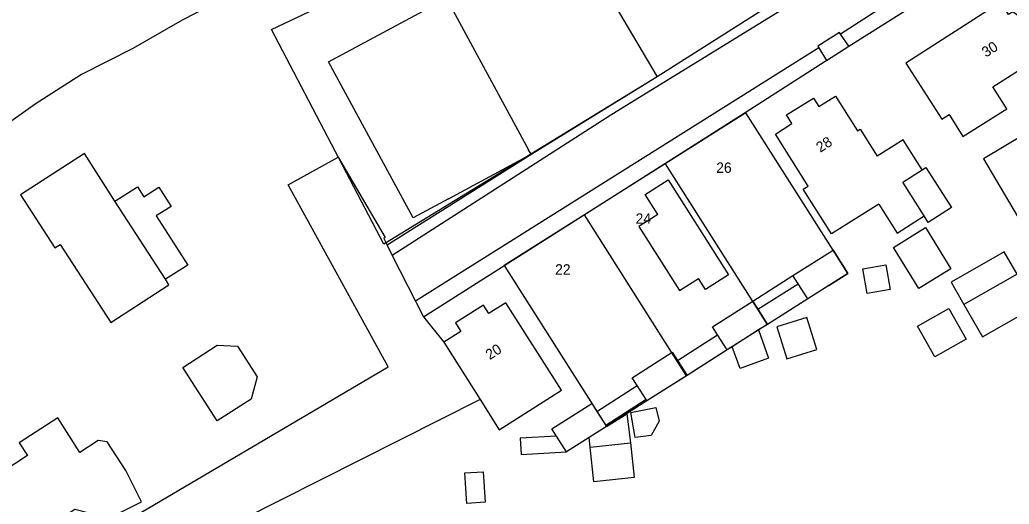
# Model space of a CAD drawing. Extents: x 194485 to 197793, y 468269 to 470822.
# Drawn here: x 195533.1 to 195647.3, y 469392.9 to 469448.8 of the extents above; entities that cross this region are included whole.
import ezdxf

# ---------------------------------------------------------------- set-up
doc = ezdxf.new("R2010")
doc.units = 0
for name, color, linetype in [('BAG standplaatsen grensvlak', 7, 'Continuous'), ('BAG standplaatsen grensvlak LR', 7, 'Continuous'), ('BAG standplaatsen kenmerkpunt', 7, 'Continuous'), ('BGT grensvlak gebouwinstallatie plus 1', 7, 'Continuous'), ('BGT grensvlak onbegroeid terreindeel', 7, 'Continuous'), ('BGT grensvlak overig bouwwerk uitbreiding populatie', 7, 'Continuous'), ('BGT grensvlak pand op maaiveld', 7, 'Continuous'), ('BGT grensvlak pand op maaiveld LR', 7, 'Continuous'), ('BGT grensvlak wegdeel', 7, 'Continuous'), ('BGT tekst huisnummerreeks', 7, 'Continuous')]:
    doc.layers.add(name, color=color, linetype=linetype)

msp = doc.modelspace()

# ---------------------------------------------------------------- linework, layer by layer
at = {"layer": 'BAG standplaatsen grensvlak'}
for p, q in [((195616.89, 469438.07), (195607.58, 469432.19)), ((195607.58, 469432.19), (195598.28, 469426.31)), ((195598.28, 469426.31), (195589.01, 469420.46)), ((195589.01, 469420.46), (195600.82, 469401.86)), ((195626.46, 469418.14), (195628.67, 469419.55)), ((195619.36, 469413.63), (195618.84, 469413.3)), ((195603.25, 469403.4), (195600.82, 469401.86))]:
    msp.add_line(p, q, dxfattribs=at)
for points in [[(195562.14, 469447.72), (195594.39, 469463), (195606.67, 469442.23), (195575.13, 469422.91), (195562.14, 469447.72)], [(195628.67, 469419.55), (195626.97, 469422.23), (195616.89, 469438.07)], [(195626.46, 469418.14), (195624.04, 469416.6), (195619.39, 469413.66), (195619.36, 469413.63)], [(195618.84, 469413.3), (195614.75, 469410.71), (195611.14, 469408.41)], [(195611.14, 469408.41), (195610.11, 469407.76), (195610.07, 469407.73)], [(195610.07, 469407.73), (195605.48, 469404.82), (195603.25, 469403.4)]]:
    msp.add_lwpolyline(points, dxfattribs=at)
at = {"layer": 'BAG standplaatsen grensvlak LR'}
for p, q in [((195607.58, 469432.19), (195619.36, 469413.63)), ((195610.07, 469407.73), (195598.28, 469426.31))]:
    msp.add_line(p, q, dxfattribs=at)
at = {"layer": 'BGT grensvlak gebouwinstallatie plus 1'}
for p, q in [((195544.09, 469427.9), (195546.68, 469429.55)), ((195546.68, 469429.55), (195547.42, 469428.39)), ((195547.42, 469428.39), (195549.15, 469429.49)), ((195549.15, 469429.49), (195550.56, 469427.28)), ((195550.56, 469427.28), (195548.86, 469426.19)), ((195548.86, 469426.19), (195552.49, 469420.49)), ((195633.94, 469422.55), (195637.63, 469424.83)), ((195637.63, 469424.83), (195640.56, 469420.07)), ((195636.86, 469417.8), (195633.94, 469422.55)), ((195552.49, 469420.49), (195549.92, 469418.86)), ((195640.56, 469420.07), (195636.86, 469417.8)), ((195617.69, 469416.34), (195622.33, 469419.29)), ((195618.29, 469415.4), (195622.93, 469418.35)), ((195624.04, 469416.6), (195619.39, 469413.66)), ((195636.71, 469413.45), (195640.33, 469415.49)), ((195640.33, 469415.49), (195642.34, 469411.94)), ((195618.37, 469413.01), (195619.53, 469409.77)), ((195638.71, 469409.9), (195636.71, 469413.45)), ((195609.02, 469409.47), (195613.64, 469412.46)), ((195642.34, 469411.94), (195638.71, 469409.9)), ((195551.92, 469408.69), (195555.88, 469411.24)), ((195555.88, 469411.24), (195558.22, 469411.13)), ((195558.22, 469411.13), (195560.49, 469407.59)), ((195614.75, 469410.71), (195610.11, 469407.76)), ((195616.23, 469408.58), (195615.33, 469411.07)), ((195619.53, 469409.77), (195616.23, 469408.58)), ((195555.9, 469402.51), (195551.92, 469408.69)), ((195560.49, 469407.59), (195559.82, 469405.04)), ((195599.71, 469403.61), (195604.35, 469406.59)), ((195559.82, 469405.04), (195555.9, 469402.51)), ((195605.38, 469404.97), (195600.74, 469401.99)), ((195600.82, 469401.86), (195603.15, 469403.34)), ((195603.15, 469403.34), (195603.6, 469399.99)), ((195598.92, 469399.49), (195598.81, 469400.58))]:
    msp.add_line(p, q, dxfattribs=at)
for points in [[(195648.2, 469419.44), (195646.73, 469422.02), (195640.6, 469418.52), (195642.07, 469415.94)], [(195595.05, 469400.75), (195590.86, 469400.52), (195590.96, 469398.63), (195596.21, 469398.93)], [(195584.71, 469392.97), (195584.46, 469396.5), (195586.58, 469396.65), (195586.83, 469393.12), (195584.71, 469392.97)]]:
    msp.add_lwpolyline(points, dxfattribs=at)
at = {"layer": 'BGT grensvlak onbegroeid terreindeel'}
for p, q in [((195569.87, 469432.96), (195575.29, 469423.67)), ((195579.69, 469414.54), (195582.04, 469411.6))]:
    msp.add_line(p, q, dxfattribs=at)
for points in [[(195557.58, 469458.08), (195556.67, 469451.29), (195551.86, 469448.79), (195546.14, 469445.52), (195540.23, 469442.5), (195534.89, 469439.09), (195530.98, 469436.3), (195524.59, 469433.08)], [(195586.25, 469404.97), (195544.72, 469384.03), (195542.2, 469389.04), (195575.62, 469408.74), (195564.07, 469429.77), (195569.87, 469432.96)], [(195575.29, 469423.67), (195575.11, 469423.56), (195575.5, 469422.79)]]:
    msp.add_lwpolyline(points, dxfattribs=at)
at = {"layer": 'BGT grensvlak overig bouwwerk uitbreiding populatie'}
for p, q in [((195630.42, 469420.07), (195633.05, 469420.53)), ((195630.91, 469417.23), (195630.42, 469420.07)), ((195633.05, 469420.53), (195633.54, 469417.69)), ((195633.54, 469417.69), (195630.91, 469417.23)), ((195603.61, 469403.49), (195606.51, 469404.07)), ((195604.14, 469400.6), (195603.61, 469403.49)), ((195606.51, 469404.07), (195606.88, 469402.48)), ((195606.88, 469402.48), (195605.96, 469400.82)), ((195605.96, 469400.82), (195604.14, 469400.6))]:
    msp.add_line(p, q, dxfattribs=at)
for points in [[(195606.73, 469426.36), (195605.28, 469428.65), (195607.94, 469430.34), (195614.91, 469419.36), (195612.25, 469417.68), (195611.45, 469418.94)], [(195606.73, 469426.36), (195604.54, 469424.97), (195609.25, 469417.55), (195611.45, 469418.94)]]:
    msp.add_lwpolyline(points, dxfattribs=at)
at = {"layer": 'BGT grensvlak pand op maaiveld'}
for p, q in [((195630.1, 469436.18), (195632.05, 469433.09)), ((195549.92, 469418.86), (195544.09, 469427.9)), ((195648.2, 469419.44), (195642.07, 469415.94)), ((195622.93, 469418.35), (195622.33, 469419.29)), ((195624.04, 469416.6), (195622.93, 469418.35)), ((195617.69, 469416.34), (195618.29, 469415.4)), ((195618.29, 469415.4), (195619.39, 469413.66)), ((195623.94, 469414.45), (195620.47, 469413.37)), ((195625.1, 469410.76), (195623.94, 469414.45)), ((195618.37, 469413.01), (195615.33, 469411.07)), ((195619.39, 469413.66), (195618.37, 469413.01)), ((195620.47, 469413.37), (195621.62, 469409.68)), ((195582.04, 469411.6), (195586.25, 469404.97)), ((195614.75, 469410.71), (195613.64, 469412.46)), ((195615.33, 469411.07), (195614.75, 469410.71)), ((195621.62, 469409.68), (195625.1, 469410.76)), ((195609.02, 469409.47), (195610.11, 469407.76)), ((195610.11, 469407.76), (195605.48, 469404.82)), ((195605.38, 469404.97), (195604.35, 469406.59)), ((195605.48, 469404.82), (195605.38, 469404.97)), ((195599.71, 469403.61), (195600.74, 469401.99)), ((195600.82, 469401.86), (195598.81, 469400.58)), ((195600.74, 469401.99), (195600.82, 469401.86)), ((195596.21, 469398.93), (195595.05, 469400.75)), ((195598.81, 469400.58), (195596.21, 469398.93)), ((195598.92, 469399.49), (195603.6, 469399.99)), ((195603.6, 469399.99), (195604.03, 469395.98)), ((195599.35, 469395.47), (195598.92, 469399.49)), ((195604.03, 469395.98), (195599.35, 469395.47))]:
    msp.add_line(p, q, dxfattribs=at)
for points in [[(195582.6, 469428.15), (195578.5, 469425.94), (195568.75, 469443.96), (195582.35, 469451.33), (195591.83, 469433.82)], [(195635.38, 469443.83), (195639.51, 469437.33), (195640.35, 469437.87), (195641.96, 469435.34), (195647.03, 469438.55), (195645.42, 469441.09), (195650.49, 469444.31), (195649.58, 469445.74), (195650.06, 469446.05), (195649.86, 469446.99), (195649.55, 469447.81), (195649.07, 469448.54), (195648.47, 469449.17), (195647.72, 469449.75), (195647.23, 469449.44), (195646.34, 469450.84), (195635.38, 469443.83)], [(195623.52, 469429.27), (195624.08, 469429.62), (195620.32, 469435.63), (195622.22, 469436.84), (195621.61, 469437.83), (195624.71, 469439.79), (195625.34, 469438.82), (195627.25, 469440.02), (195629.8, 469435.99), (195630.1, 469436.18)], [(195644.32, 469432.76), (195648.22, 469426.18), (195657.6, 469431.78), (195653.69, 469438.36), (195644.32, 469432.76)], [(195637.24, 469431.49), (195635.04, 469434.98), (195632.05, 469433.09)], [(195544.09, 469427.9), (195540.57, 469433.38), (195533.2, 469428.61)], [(195582.6, 469428.15), (195592.11, 469433.3), (195591.83, 469433.82)], [(195637.24, 469431.49), (195637.69, 469431.78), (195640.62, 469427.14), (195637.94, 469425.43), (195637.48, 469426.17)], [(195533.2, 469428.61), (195537.17, 469422.48), (195537.78, 469422.87), (195543.6, 469413.89), (195550.32, 469418.23), (195549.92, 469418.86)], [(195632.23, 469427.55), (195626.79, 469424.11), (195623.52, 469429.27)], [(195632.23, 469427.55), (195634.36, 469424.19), (195637.48, 469426.17)], [(195622.33, 469419.29), (195626.97, 469422.23), (195628.67, 469419.55), (195624.04, 469416.6)], [(195642.07, 469415.94), (195644.2, 469412.2), (195653.96, 469417.77), (195651.83, 469421.51), (195648.2, 469419.44)], [(195586.25, 469404.97), (195588.45, 469401.5), (195595.62, 469406.05), (195589.21, 469416.16), (195587.47, 469415.05), (195587.24, 469414.9), (195586.62, 469415.86), (195583.4, 469413.83), (195584.01, 469412.85), (195582.04, 469411.6)], [(195613.64, 469412.46), (195613.05, 469413.39), (195617.69, 469416.34)], [(195604.35, 469406.59), (195603.77, 469407.5), (195608.4, 469410.44), (195609.02, 469409.47)], [(195595.05, 469400.75), (195594.5, 469401.61), (195599.12, 469404.54), (195599.71, 469403.61)], [(195540.04, 469398.88), (195537.48, 469402.85), (195533.03, 469399.98), (195533.98, 469398.53), (195526.76, 469393.79), (195531.16, 469386.93), (195539.46, 469392.31)], [(195545.36, 469396.8), (195543.21, 469400.08), (195542.15, 469400.26), (195540.04, 469398.88)], [(195539.46, 469392.31), (195541.12, 469391.9), (195541.82, 469390.5), (195547.17, 469393.16), (195545.36, 469396.8)]]:
    msp.add_lwpolyline(points, dxfattribs=at)
at = {"layer": 'BGT grensvlak pand op maaiveld LR'}
for p, q in [((195635.01, 469430.08), (195637.24, 469431.49)), ((195637.48, 469426.17), (195635.01, 469430.08))]:
    msp.add_line(p, q, dxfattribs=at)
at = {"layer": 'BGT grensvlak wegdeel'}
for p, q in [((195643.77, 469457.44), (195627.83, 469447.18)), ((195628.8, 469445.77), (195643.99, 469455.41)), ((195628.8, 469445.77), (195627.83, 469447.18)), ((195626.22, 469444.14), (195628.8, 469445.77)), ((195625.33, 469445.58), (195578.77, 469416.35)), ((195625.33, 469445.58), (195626.22, 469444.14)), ((195575.5, 469422.79), (195576.1, 469421.6)), ((195576.1, 469421.6), (195578.77, 469416.35)), ((195578.77, 469416.35), (195578.89, 469416.1)), ((195578.89, 469416.1), (195579.69, 469414.54))]:
    msp.add_line(p, q, dxfattribs=at)
for points in [[(195639.88, 469463.33), (195606.67, 469442.23), (195592.19, 469433.3), (195575.5, 469422.79)], [(195640.88, 469462.46), (195627.02, 469453.68), (195601.44, 469437.89), (195576.1, 469421.6)], [(195627.83, 469447.18), (195627.7, 469447.37), (195625.21, 469445.78), (195625.33, 469445.58)], [(195579.69, 469414.54), (195616.84, 469438.12), (195626.05, 469444.03), (195626.22, 469444.14)]]:
    msp.add_lwpolyline(points, dxfattribs=at)

# ---------------------------------------------------------------- texts
at = {"layer": 'BAG standplaatsen kenmerkpunt'}
for s, p in [('26', (195613.48, 469431.15)), ('24', (195604.18, 469425.27)), ('22', (195594.89, 469419.4))]:
    msp.add_text(s, height=1.2, dxfattribs=at).set_placement(p)
at = {"layer": 'BGT tekst huisnummerreeks'}
for s, p in [('30', (195644.61, 469444.44)), ('28', (195625.49, 469433.46)), ('20', (195587.34, 469409.52))]:
    msp.add_text(s, height=1.2, rotation=32.4, dxfattribs=at).set_placement(p)

doc.saveas('drawing.dxf')
